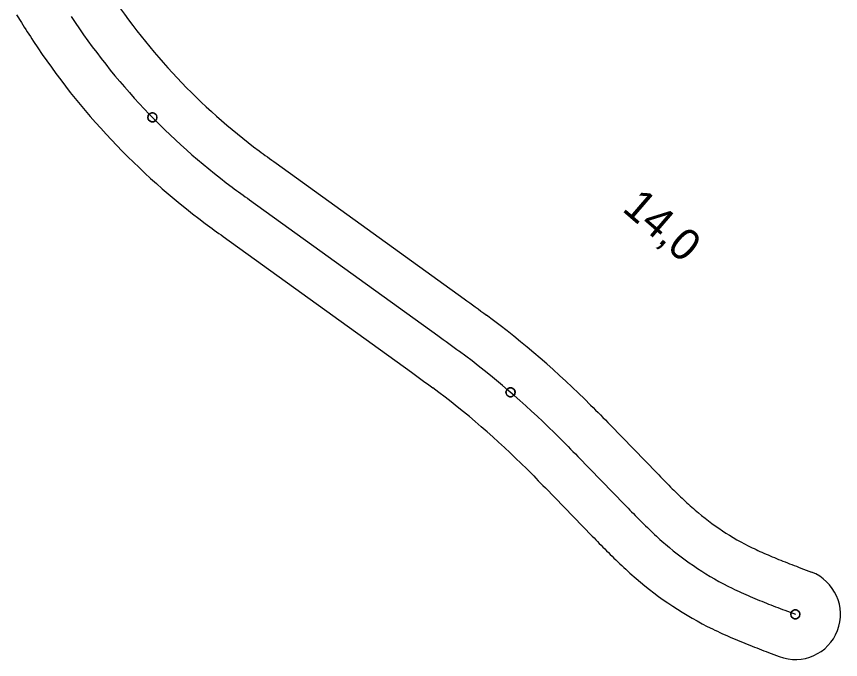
# Model space of a CAD drawing. Extents: x -670810 to -649614, y -1131928 to -1115069.
# Drawn here: x -667422 to -665597, y -1130869 to -1129446 of the extents above; entities that cross this region are included whole.
import ezdxf

# ---------------------------------------------------------------- set-up
doc = ezdxf.new("R2010")
doc.units = 0
for name, color, linetype in [('hranice_VRT_ZUR_Vysocina', 7, 'Continuous'), ('Osa koleje úprava GPK', 7, 'Continuous'), ('Situace - Osa koleje 2D', 7, 'Continuous'), ('Situace - Osa koleje tunel 2D', 7, 'Continuous'), ('Staničení - hlavní staničení + kolečka 1k', 7, 'Continuous')]:
    doc.layers.add(name, color=color, linetype=linetype)

# ---------------------------------------------------------------- blocks, each defined once
blk = doc.blocks.new('Sit10Kruh_179')
at = {"layer": 'Staničení - hlavní staničení + kolečka 1k'}
blk.add_lwpolyline([(10, 0), (9.98026, 0.6279), (9.92114, 1.25334), (9.82288, 1.87382), (9.68584, 2.4869), (9.51056, 3.09016), (9.29776, 3.68124), (9.04828, 4.2578), (8.76306, 4.81754), (8.44328, 5.35826), (8.09016, 5.87786), (7.70514, 6.37424), (7.28968, 6.84548), (6.84548, 7.28968), (6.37424, 7.70514), (5.87786, 8.09016), (5.35826, 8.44328), (4.81754, 8.76306), (4.2578, 9.04828), (3.68124, 9.29776), (3.09016, 9.51056), (2.4869, 9.68584), (1.87382, 9.82288), (1.25334, 9.92114), (0.6279, 9.98026), (0, 10), (-0.6279, 9.98026), (-1.25334, 9.92114), (-1.87382, 9.82288), (-2.4869, 9.68584), (-3.09016, 9.51056), (-3.68124, 9.29776), (-4.2578, 9.04828), (-4.81754, 8.76306), (-5.35826, 8.44328), (-5.87786, 8.09016), (-6.37424, 7.70514), (-6.84548, 7.28968), (-7.28968, 6.84548), (-7.70514, 6.37424), (-8.09016, 5.87786), (-8.44328, 5.35826), (-8.76306, 4.81754), (-9.04828, 4.2578), (-9.29776, 3.68124), (-9.51056, 3.09016), (-9.68584, 2.4869), (-9.82288, 1.87382), (-9.92114, 1.25334), (-9.98026, 0.6279), (-10, 0), (-9.98026, -0.6279), (-9.92114, -1.25334), (-9.82288, -1.87382), (-9.68584, -2.4869), (-9.51056, -3.09016), (-9.29776, -3.68124), (-9.04828, -4.2578), (-8.76306, -4.81754), (-8.44328, -5.35826), (-8.09016, -5.87786), (-7.70514, -6.37424), (-7.28968, -6.84548), (-6.84548, -7.28968), (-6.37424, -7.70514), (-5.87786, -8.09016), (-5.35826, -8.44328), (-4.81754, -8.76306), (-4.2578, -9.04828), (-3.68124, -9.29776), (-3.09016, -9.51056), (-2.4869, -9.68584), (-1.87382, -9.82288), (-1.25334, -9.92114), (-0.6279, -9.98026), (0, -10), (0.6279, -9.98026), (1.25334, -9.92114), (1.87382, -9.82288), (2.4869, -9.68584), (3.09016, -9.51056), (3.68124, -9.29776), (4.2578, -9.04828), (4.81754, -8.76306), (5.35826, -8.44328), (5.87786, -8.09016), (6.37424, -7.70514), (6.84548, -7.28968), (7.28968, -6.84548), (7.70514, -6.37424), (8.09016, -5.87786), (8.44328, -5.35826), (8.76306, -4.81754), (9.04828, -4.2578), (9.29776, -3.68124), (9.51056, -3.09016), (9.68584, -2.4869), (9.82288, -1.87382), (9.92114, -1.25334)], close=True, dxfattribs=at)
blk.add_circle((0, 0), 10, dxfattribs=at)
blk = doc.blocks.new('Sit10Kruh_180')
at = {"layer": 'Staničení - hlavní staničení + kolečka 1k'}
blk.add_lwpolyline([(10, 0), (10, 0.6), (9.9, 1.3), (9.8, 1.9), (9.7, 2.5), (9.5, 3.1), (9.3, 3.7), (9, 4.3), (8.8, 4.8), (8.4, 5.4), (8.1, 5.9), (7.7, 6.4), (7.3, 6.8), (6.8, 7.3), (6.4, 7.7), (5.9, 8.1), (5.4, 8.4), (4.8, 8.8), (4.3, 9), (3.7, 9.3), (3.1, 9.5), (2.5, 9.7), (1.9, 9.8), (1.3, 9.9), (0.6, 10), (0, 10), (-0.6, 10), (-1.3, 9.9), (-1.9, 9.8), (-2.5, 9.7), (-3.1, 9.5), (-3.7, 9.3), (-4.3, 9), (-4.8, 8.8), (-5.4, 8.4), (-5.9, 8.1), (-6.4, 7.7), (-6.8, 7.3), (-7.3, 6.8), (-7.7, 6.4), (-8.1, 5.9), (-8.4, 5.4), (-8.8, 4.8), (-9, 4.3), (-9.3, 3.7), (-9.5, 3.1), (-9.7, 2.5), (-9.8, 1.9), (-9.9, 1.3), (-10, 0.6), (-10, 0), (-10, -0.6), (-9.9, -1.3), (-9.8, -1.9), (-9.7, -2.5), (-9.5, -3.1), (-9.3, -3.7), (-9, -4.3), (-8.8, -4.8), (-8.4, -5.4), (-8.1, -5.9), (-7.7, -6.4), (-7.3, -6.8), (-6.8, -7.3), (-6.4, -7.7), (-5.9, -8.1), (-5.4, -8.4), (-4.8, -8.8), (-4.3, -9), (-3.7, -9.3), (-3.1, -9.5), (-2.5, -9.7), (-1.9, -9.8), (-1.3, -9.9), (-0.6, -10), (0, -10), (0.6, -10), (1.3, -9.9), (1.9, -9.8), (2.5, -9.7), (3.1, -9.5), (3.7, -9.3), (4.3, -9), (4.8, -8.8), (5.4, -8.4), (5.9, -8.1), (6.4, -7.7), (6.8, -7.3), (7.3, -6.8), (7.7, -6.4), (8.1, -5.9), (8.4, -5.4), (8.8, -4.8), (9, -4.3), (9.3, -3.7), (9.5, -3.1), (9.7, -2.5), (9.8, -1.9), (9.9, -1.3)], close=True, dxfattribs=at)
blk.add_circle((0, 0), 10, dxfattribs=at)
blk = doc.blocks.new('Sit10Kruh_181')
at = {"layer": 'Staničení - hlavní staničení + kolečka 1k'}
blk.add_lwpolyline([(10, 0), (10, 0.6), (9.9, 1.3), (9.8, 1.9), (9.7, 2.5), (9.5, 3.1), (9.3, 3.7), (9, 4.3), (8.8, 4.8), (8.4, 5.4), (8.1, 5.9), (7.7, 6.4), (7.3, 6.8), (6.8, 7.3), (6.4, 7.7), (5.9, 8.1), (5.4, 8.4), (4.8, 8.8), (4.3, 9), (3.7, 9.3), (3.1, 9.5), (2.5, 9.7), (1.9, 9.8), (1.3, 9.9), (0.6, 10), (0, 10), (-0.6, 10), (-1.3, 9.9), (-1.9, 9.8), (-2.5, 9.7), (-3.1, 9.5), (-3.7, 9.3), (-4.3, 9), (-4.8, 8.8), (-5.4, 8.4), (-5.9, 8.1), (-6.4, 7.7), (-6.8, 7.3), (-7.3, 6.8), (-7.7, 6.4), (-8.1, 5.9), (-8.4, 5.4), (-8.8, 4.8), (-9, 4.3), (-9.3, 3.7), (-9.5, 3.1), (-9.7, 2.5), (-9.8, 1.9), (-9.9, 1.3), (-10, 0.6), (-10, 0), (-10, -0.6), (-9.9, -1.3), (-9.8, -1.9), (-9.7, -2.5), (-9.5, -3.1), (-9.3, -3.7), (-9, -4.3), (-8.8, -4.8), (-8.4, -5.4), (-8.1, -5.9), (-7.7, -6.4), (-7.3, -6.8), (-6.8, -7.3), (-6.4, -7.7), (-5.9, -8.1), (-5.4, -8.4), (-4.8, -8.8), (-4.3, -9), (-3.7, -9.3), (-3.1, -9.5), (-2.5, -9.7), (-1.9, -9.8), (-1.3, -9.9), (-0.6, -10), (0, -10), (0.6, -10), (1.3, -9.9), (1.9, -9.8), (2.5, -9.7), (3.1, -9.5), (3.7, -9.3), (4.3, -9), (4.8, -8.8), (5.4, -8.4), (5.9, -8.1), (6.4, -7.7), (6.8, -7.3), (7.3, -6.8), (7.7, -6.4), (8.1, -5.9), (8.4, -5.4), (8.8, -4.8), (9, -4.3), (9.3, -3.7), (9.5, -3.1), (9.7, -2.5), (9.8, -1.9), (9.9, -1.3)], close=True, dxfattribs=at)
blk.add_circle((0, 0), 10, dxfattribs=at)
blk = doc.blocks.new('Sit10Kruh_182')
at = {"layer": 'Staničení - hlavní staničení + kolečka 1k'}
blk.add_lwpolyline([(10, 0), (10, 0.6), (9.9, 1.3), (9.8, 1.9), (9.7, 2.5), (9.5, 3.1), (9.3, 3.7), (9, 4.3), (8.8, 4.8), (8.4, 5.4), (8.1, 5.9), (7.7, 6.4), (7.3, 6.8), (6.8, 7.3), (6.4, 7.7), (5.9, 8.1), (5.4, 8.4), (4.8, 8.8), (4.3, 9), (3.7, 9.3), (3.1, 9.5), (2.5, 9.7), (1.9, 9.8), (1.3, 9.9), (0.6, 10), (0, 10), (-0.6, 10), (-1.3, 9.9), (-1.9, 9.8), (-2.5, 9.7), (-3.1, 9.5), (-3.7, 9.3), (-4.3, 9), (-4.8, 8.8), (-5.4, 8.4), (-5.9, 8.1), (-6.4, 7.7), (-6.8, 7.3), (-7.3, 6.8), (-7.7, 6.4), (-8.1, 5.9), (-8.4, 5.4), (-8.8, 4.8), (-9, 4.3), (-9.3, 3.7), (-9.5, 3.1), (-9.7, 2.5), (-9.8, 1.9), (-9.9, 1.3), (-10, 0.6), (-10, 0), (-10, -0.6), (-9.9, -1.3), (-9.8, -1.9), (-9.7, -2.5), (-9.5, -3.1), (-9.3, -3.7), (-9, -4.3), (-8.8, -4.8), (-8.4, -5.4), (-8.1, -5.9), (-7.7, -6.4), (-7.3, -6.8), (-6.8, -7.3), (-6.4, -7.7), (-5.9, -8.1), (-5.4, -8.4), (-4.8, -8.8), (-4.3, -9), (-3.7, -9.3), (-3.1, -9.5), (-2.5, -9.7), (-1.9, -9.8), (-1.3, -9.9), (-0.6, -10), (0, -10), (0.6, -10), (1.3, -9.9), (1.9, -9.8), (2.5, -9.7), (3.1, -9.5), (3.7, -9.3), (4.3, -9), (4.8, -8.8), (5.4, -8.4), (5.9, -8.1), (6.4, -7.7), (6.8, -7.3), (7.3, -6.8), (7.7, -6.4), (8.1, -5.9), (8.4, -5.4), (8.8, -4.8), (9, -4.3), (9.3, -3.7), (9.5, -3.1), (9.7, -2.5), (9.8, -1.9), (9.9, -1.3)], close=True, dxfattribs=at)
blk.add_circle((0, 0), 10, dxfattribs=at)

msp = doc.modelspace()

# ---------------------------------------------------------------- linework, layer by layer
at = {"layer": 'hranice_VRT_ZUR_Vysocina'}
for points in [[(-667421.6, -1129442.4), (-667410.8, -1129459.2), (-667407.6, -1129464.3), (-667404.3, -1129469.4), (-667401.1, -1129474.6), (-667397.7, -1129479.8), (-667394.4, -1129485), (-667390.9, -1129490.3), (-667387.5, -1129495.6), (-667384.1, -1129500.9), (-667384, -1129500.9)], [(-666884.6, -1129743.2), (-666880, -1129746.6), (-666875.4, -1129750), (-666870.8, -1129753.3), (-666866.1, -1129756.7), (-666861.4, -1129760.2), (-666856.6, -1129763.6), (-666851.8, -1129767.1), (-666847, -1129770.6), (-666430.6, -1130070.7), (-666424.5, -1130075.1), (-666418.3, -1130079.5), (-666412.1, -1130084), (-666405.9, -1130088.5), (-666399.7, -1130093), (-666393.4, -1130097.6), (-666387.2, -1130102.2), (-666380.9, -1130106.8), (-666380.9, -1130106.9)], [(-667004, -1129903.6), (-667003.9, -1129903.7), (-666998.9, -1129907.4), (-666993.8, -1129911.2), (-666988.7, -1129914.9), (-666983.7, -1129918.5), (-666978.7, -1129922.2), (-666973.7, -1129925.7), (-666968.8, -1129929.3), (-666963.9, -1129932.8), (-666547.5, -1130232.9), (-666541.4, -1130237.3), (-666535.4, -1130241.6), (-666529.4, -1130246), (-666523.5, -1130250.3), (-666517.6, -1130254.6), (-666511.8, -1130258.8), (-666506, -1130263.1), (-666500.1, -1130267.4)], [(-666150.6, -1130305.5), (-666150.6, -1130305.6), (-666145.1, -1130311.1), (-666139.6, -1130316.6), (-666134.2, -1130322.1), (-666128.8, -1130327.6), (-666123.4, -1130333.1), (-666118.1, -1130338.6), (-666112.8, -1130344), (-666107.6, -1130349.4), (-666003.5, -1130456.3), (-665999.7, -1130460.3), (-665996, -1130464.2), (-665992.2, -1130468), (-665988.4, -1130471.8), (-665984.7, -1130475.7), (-665981, -1130479.4), (-665977.3, -1130483.2), (-665973.6, -1130486.9), (-665970, -1130490.6), (-665966.3, -1130494.2), (-665962.7, -1130497.8), (-665959.1, -1130501.4), (-665955.5, -1130504.9), (-665951.8, -1130508.4), (-665948.2, -1130511.8), (-665944.6, -1130515.2), (-665941.1, -1130518.6), (-665937.5, -1130521.9), (-665933.9, -1130525.2), (-665930.3, -1130528.4), (-665926.8, -1130531.6), (-665923.2, -1130534.7), (-665919.5, -1130537.9)], [(-666292, -1130447), (-666286.9, -1130452.2), (-666281.8, -1130457.3), (-666276.7, -1130462.4), (-666271.6, -1130467.6), (-666266.5, -1130472.9), (-666261.3, -1130478.1), (-666256.1, -1130483.5), (-666250.9, -1130488.8), (-666146.9, -1130595.8), (-666143.1, -1130599.7), (-666139.2, -1130603.7), (-666135.4, -1130607.7), (-666131.4, -1130611.7), (-666127.5, -1130615.7), (-666123.5, -1130619.7), (-666119.5, -1130623.8), (-666115.5, -1130627.9), (-666111.4, -1130632), (-666107.3, -1130636.1), (-666103.2, -1130640.2), (-666099, -1130644.3), (-666094.8, -1130648.4), (-666090.5, -1130652.5), (-666086.2, -1130656.6), (-666081.8, -1130660.8), (-666077.4, -1130664.9), (-666073, -1130669), (-666068.4, -1130673.2), (-666063.9, -1130677.3), (-666059.3, -1130681.4), (-666054.6, -1130685.5), (-666050, -1130689.4), (-666049.9, -1130689.6)], [(-665793.2, -1130621.2), (-665788.8, -1130623.3), (-665784.5, -1130625.4), (-665780.2, -1130627.4), (-665775.8, -1130629.4), (-665771.4, -1130631.4), (-665766.9, -1130633.4), (-665762.4, -1130635.3), (-665757.9, -1130637.3), (-665753.3, -1130639.2), (-665748.6, -1130641.2), (-665744, -1130643.1), (-665739.3, -1130645), (-665734.5, -1130647), (-665729.7, -1130648.9), (-665724.9, -1130650.8), (-665720, -1130652.7), (-665715.2, -1130654.6), (-665710.2, -1130656.6), (-665705.3, -1130658.5), (-665700.3, -1130660.4), (-665695.2, -1130662.3), (-665690.2, -1130664.3), (-665685.1, -1130666.2), (-665661.7, -1130675.2)], [(-665881.1, -1130800.8), (-665880.9, -1130800.9), (-665875.5, -1130803.5), (-665869.9, -1130806.2), (-665864.3, -1130808.8), (-665858.7, -1130811.4), (-665853.1, -1130813.9), (-665847.6, -1130816.4), (-665842.1, -1130818.8), (-665836.5, -1130821.2), (-665831, -1130823.5), (-665825.6, -1130825.8), (-665820.1, -1130828.1), (-665814.7, -1130830.3), (-665809.3, -1130832.5), (-665803.9, -1130834.6), (-665798.5, -1130836.8), (-665793.2, -1130838.9), (-665787.9, -1130840.9), (-665782.6, -1130843), (-665777.4, -1130845), (-665772.1, -1130847), (-665766.9, -1130849), (-665761.8, -1130851), (-665756.6, -1130853), (-665733.3, -1130861.9)]]:
    msp.add_lwpolyline(points, dxfattribs=at)
for centre, radius, start, end in [((-666047.9, -1128620.7), 1400, 213.3813, 233.3002), ((-666047.9, -1128620.7), 1600, 213.3775, 233.3041), ((-667634.1, -1131792), 2100, 45.0583, 53.3614), ((-667634.1, -1131792), 1900, 45.0609, 53.3587), ((-665528.8, -1130082.6), 600, 229.3731, 243.8556), ((-665697.5, -1130768.6), 100, 249.0299, 69.0299), ((-665528.8, -1130082.6), 800, 229.3554, 243.8733)]:
    msp.add_arc(centre, radius, start, end, dxfattribs=at)
at = {"layer": 'Osa koleje úprava GPK'}
msp.add_line((-665720.8, -1130759.6), (-665697.5, -1130768.6), dxfattribs=at)
msp.add_line((-665720.8, -1130759.6), (-665697.5, -1130768.6), dxfattribs=at)
at = {"layer": 'Situace - Osa koleje 2D'}
for p, q in [((-666179.2, -1130419.1), (-666075.2, -1130526.1)), ((-665720.8, -1130759.6), (-665697.5, -1130768.6))]:
    msp.add_line(p, q, dxfattribs=at)
for points in [[(-666221.3, -1130376.3), (-666216, -1130381.6), (-666210.7, -1130386.9), (-666205.4, -1130392.3), (-666200.2, -1130397.6), (-666194.9, -1130403), (-666189.7, -1130408.4), (-666184.5, -1130413.7), (-666179.2, -1130419.1)], [(-666075.2, -1130526.1), (-666071.4, -1130530), (-666067.6, -1130533.9), (-666063.8, -1130537.8), (-666059.9, -1130541.8), (-666056.1, -1130545.7), (-666052.3, -1130549.6), (-666048.4, -1130553.5), (-666044.6, -1130557.4), (-666040.7, -1130561.3), (-666036.8, -1130565.1), (-666032.9, -1130569), (-666029, -1130572.8), (-666025.1, -1130576.6), (-666021.2, -1130580.4), (-666017.2, -1130584.2), (-666013.2, -1130588), (-666009.2, -1130591.8), (-666005.2, -1130595.5), (-666001.2, -1130599.2), (-665997.1, -1130602.8), (-665993, -1130606.5), (-665988.9, -1130610.1), (-665984.8, -1130613.7)], [(-665837.1, -1130711), (-665832.1, -1130713.4), (-665827.2, -1130715.8), (-665822.2, -1130718.1), (-665817.2, -1130720.4), (-665812.3, -1130722.6), (-665807.2, -1130724.9), (-665802.2, -1130727.1), (-665797.2, -1130729.2), (-665792.2, -1130731.4), (-665787.1, -1130733.5), (-665782, -1130735.6), (-665777, -1130737.7), (-665771.9, -1130739.7), (-665766.8, -1130741.8), (-665761.7, -1130743.8), (-665756.6, -1130745.8), (-665751.5, -1130747.8), (-665746.4, -1130749.8), (-665741.3, -1130751.8), (-665736.2, -1130753.7), (-665731.1, -1130755.7), (-665726, -1130757.7), (-665720.8, -1130759.6)]]:
    msp.add_lwpolyline(points, dxfattribs=at)
for centre, radius, start, end in [((-667634.1, -1131792), 2000, 45.0582, 45.4692), ((-665528.8, -1130082.6), 700, 229.3554, 243.8733)]:
    msp.add_arc(centre, radius, start, end, dxfattribs=at)
at = {"layer": 'Situace - Osa koleje tunel 2D'}
msp.add_line((-666905.5, -1129851.7), (-666489, -1130151.8), dxfattribs=at)
for points in [[(-666944.3, -1129823.4), (-666939.4, -1129827), (-666934.6, -1129830.6), (-666929.8, -1129834.1), (-666924.9, -1129837.6), (-666920.1, -1129841.2), (-666915.2, -1129844.7), (-666910.3, -1129848.2), (-666905.5, -1129851.7)], [(-666489, -1130151.8), (-666482.9, -1130156.2), (-666476.9, -1130160.6), (-666470.8, -1130165), (-666464.7, -1130169.4), (-666458.7, -1130173.8), (-666452.6, -1130178.2), (-666446.6, -1130182.7), (-666440.5, -1130187.1)]]:
    msp.add_lwpolyline(points, dxfattribs=at)
for centre, radius, start, end in [((-666047.9, -1128620.7), 1500, 213.3774, 233.3041), ((-667634.1, -1131792), 2000, 45.4692, 53.3614)]:
    msp.add_arc(centre, radius, start, end, dxfattribs=at)

# ---------------------------------------------------------------- block references
at = {"layer": 'Staničení - hlavní staničení + kolečka 1k'}
for name, p, rotation in [('Sit10Kruh_179', (-667120.6, -1129669.2), -45.65345400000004), ('Sit10Kruh_180', (-666328, -1130277.3), -40.76934099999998), ('Sit10Kruh_181', (-665697.5, -1130768.6), -20.970129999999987), ('Sit10Kruh_182', (-665697.5, -1130768.6), -20.970129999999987)]:
    msp.add_blockref(name, p, dxfattribs=dict(at, rotation=rotation))

# ---------------------------------------------------------------- texts
msp.add_text('14,0', height=70, rotation=319.2307, dxfattribs=at).set_placement((-666083.2, -1129874.4))

doc.saveas('drawing.dxf')
